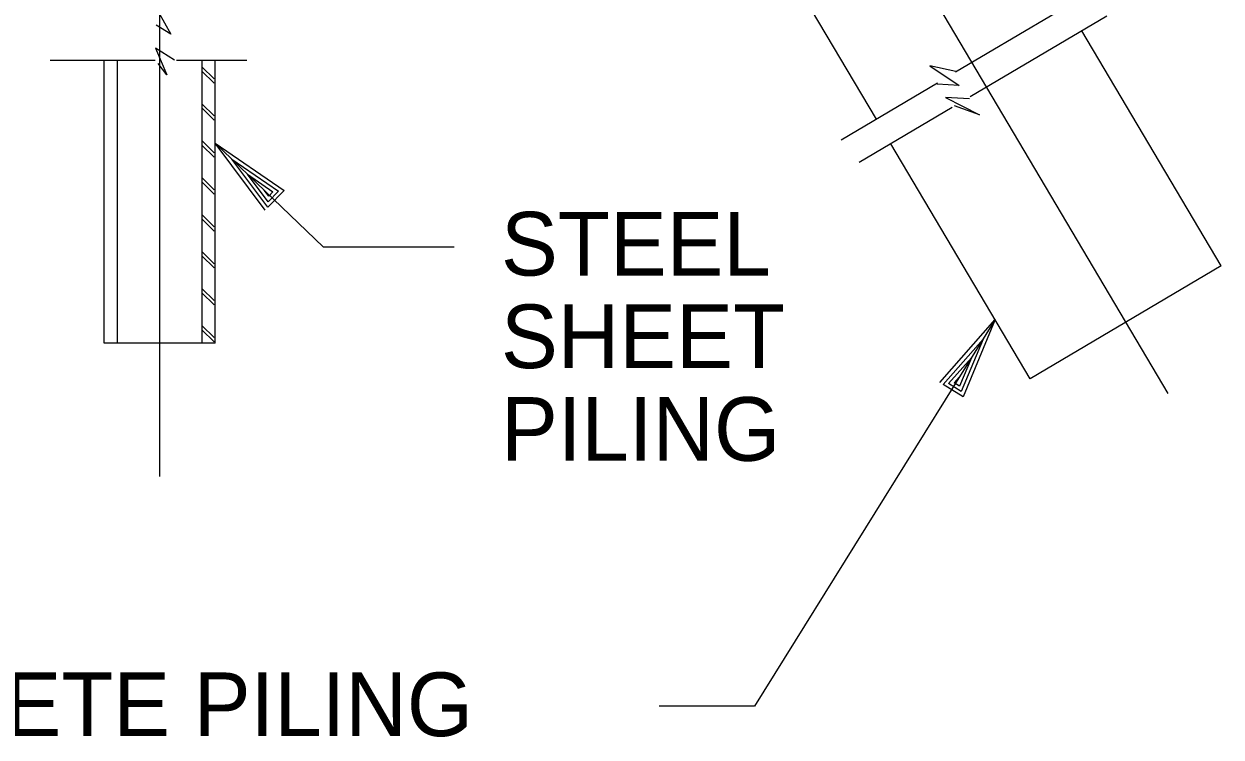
# Model space of a CAD drawing. Extents: x 44742.55 to 44745.38, y 44738.95 to 44741.13.
# Drawn here: x 44743.044 to 44743.2135, y 44740.239 to 44740.3401 of the extents above; entities that cross this region are included whole.
import ezdxf

# ---------------------------------------------------------------- set-up
doc = ezdxf.new("R2010")
doc.units = 0
for name, color, linetype in [('Level 1', 7, 'Continuous'), ('Level 2', 7, 'Continuous'), ('Level 4', 7, 'Continuous'), ('S-ANNO-DIMS', 7, 'Continuous')]:
    doc.layers.add(name, color=color, linetype=linetype)

msp = doc.modelspace()

# ---------------------------------------------------------------- linework, layer by layer
at = {"layer": 'Level 1'}
for p, q in [((44743.12366, 44740.42663), (44743.2059, 44740.28773)), ((44743.06317, 44740.40838), (44743.06317, 44740.27594)), ((44743.19454, 44740.34428), (44743.17586, 44740.33322)), ((44743.06295, 44740.34185), (44743.06477, 44740.3386)), ((44743.19726, 44740.34119), (44743.17794, 44740.32974)), ((44743.06477, 44740.3386), (44743.06268, 44740.33991)), ((44743.06525, 44740.33494), (44743.06258, 44740.33662)), ((44743.06258, 44740.33662), (44743.06419, 44740.33285)), ((44743.06252, 44740.33491), (44743.04767, 44740.33491)), ((44743.0572, 44740.29482), (44743.0572, 44740.33491)), ((44743.06419, 44740.33285), (44743.06294, 44740.33447)), ((44743.07551, 44740.33491), (44743.06554, 44740.33491)), ((44743.07087, 44740.33228), (44743.06914, 44740.334)), ((44743.1759, 44740.33333), (44743.17222, 44740.33412)), ((44743.17222, 44740.33412), (44743.17635, 44740.33134)), ((44743.07087, 44740.33166), (44743.06914, 44740.33339)), ((44743.17329, 44740.33169), (44743.15968, 44740.32362)), ((44743.17635, 44740.33134), (44743.17325, 44740.33153)), ((44743.07087, 44740.32704), (44743.06914, 44740.32877)), ((44743.17785, 44740.32946), (44743.17446, 44740.32965)), ((44743.17446, 44740.32965), (44743.17927, 44740.32719)), ((44743.17927, 44740.32719), (44743.1757, 44740.32848)), ((44743.07087, 44740.32642), (44743.06914, 44740.32816)), ((44743.17539, 44740.32823), (44743.1622, 44740.32042)), ((44743.07087, 44740.32181), (44743.06914, 44740.32353)), ((44743.07087, 44740.32119), (44743.06914, 44740.32291)), ((44743.07102, 44740.32317), (44743.07102, 44740.32317)), ((44743.07337, 44740.32092), (44743.07337, 44740.32092)), ((44743.07087, 44740.31657), (44743.06914, 44740.3183)), ((44743.07087, 44740.31596), (44743.06914, 44740.31769)), ((44743.07087, 44740.31134), (44743.06914, 44740.31307)), ((44743.07087, 44740.31073), (44743.06914, 44740.31244)), ((44743.07087, 44740.3061), (44743.06914, 44740.30784)), ((44743.07087, 44740.30549), (44743.06914, 44740.30722)), ((44743.07087, 44740.30087), (44743.06914, 44740.3026)), ((44743.07087, 44740.30026), (44743.06914, 44740.30198)), ((44743.18147, 44740.29818), (44743.18147, 44740.29818)), ((44743.07087, 44740.29563), (44743.06914, 44740.29736)), ((44743.07087, 44740.29502), (44743.06914, 44740.29675)), ((44743.17975, 44740.29542), (44743.17975, 44740.29542))]:
    msp.add_line(p, q, dxfattribs=at)
at = {"layer": 'Level 2'}
for p, q in [((44743.16466, 44740.32658), (44743.1341, 44740.37818)), ((44743.21345, 44740.3058), (44743.19374, 44740.33909)), ((44743.05531, 44740.29482), (44743.05531, 44740.33491)), ((44743.06913, 44740.33491), (44743.06913, 44740.29482)), ((44743.07102, 44740.29482), (44743.07102, 44740.33491)), ((44743.18643, 44740.2898), (44743.16671, 44740.32309)), ((44743.21345, 44740.3058), (44743.18643, 44740.2898)), ((44743.07102, 44740.29482), (44743.05531, 44740.29482))]:
    msp.add_line(p, q, dxfattribs=at)
for points in [[(44743.07102, 44740.32317), (44743.08634, 44740.30851), (44743.10486, 44740.30851)], [(44743.07812, 44740.31369), (44743.07102, 44740.32317), (44743.0808, 44740.31649), (44743.07851, 44740.31409), (44743.07337, 44740.32092), (44743.08001, 44740.31638), (44743.07854, 44740.31485), (44743.07562, 44740.31877), (44743.07921, 44740.31628), (44743.07861, 44740.31565), (44743.07797, 44740.31652)]]:
    msp.add_lwpolyline(points, dxfattribs=at)
at = {"layer": 'S-ANNO-DIMS'}
for points in [[(44743.18147, 44740.29818), (44743.14738, 44740.24343), (44743.13391, 44740.24343)], [(44743.17365, 44740.28928), (44743.18147, 44740.29818), (44743.17694, 44740.28723), (44743.17413, 44740.28898), (44743.17975, 44740.29542), (44743.17667, 44740.28799), (44743.17487, 44740.28911), (44743.1781, 44740.29277), (44743.17641, 44740.28874), (44743.17566, 44740.2892), (44743.17638, 44740.29001)]]:
    msp.add_lwpolyline(points, dxfattribs=at)

# ---------------------------------------------------------------- texts
at = {"layer": 'Level 4'}
for s, height, p in [('STEEL', 0.00902, (44743.1115, 44740.30442)), ('SHEET', 0.00902, (44743.1115, 44740.2913)), ('PILING', 0.00902, (44743.1115, 44740.27817)), ('CONCRETE PILING', 0.0090203, (44742.99697, 44740.23916))]:
    msp.add_text(s, height=height, dxfattribs=at).set_placement(p)

doc.saveas('drawing.dxf')
